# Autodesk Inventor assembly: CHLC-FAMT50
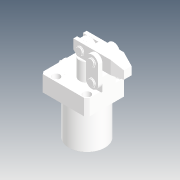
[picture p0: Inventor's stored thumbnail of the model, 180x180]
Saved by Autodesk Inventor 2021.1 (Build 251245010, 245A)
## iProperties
Created: 2019-04
Part Number: CHLC-FAMT50
Description: STEP AP214
Document SubType Name: Assembly
Designer: user
Title: CHLC-FAMT50.STEP
Revision Number: ÈÎºÎ
Sending System: SolidWorks 2016
Preprocessor: SwSTEP 2.0
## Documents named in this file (10)
- D:\Vault_2016\Projekty\Clamptek\Hydraulic\CHLC\CHLC-50\Inventor\CHLC-FAMT50\CHLC-FAMT50.iam
- D:\Vault_2016\Projekty\Clamptek\Hydraulic\CHLC\CHLC-50\Inventor\CHLC-FAMT50\CHLC-50-01.ipt
- D:\Vault_2016\Projekty\Clamptek\Hydraulic\CHLC\CHLC-50\Inventor\CHLC-FAMT50\CHLC-50-02.ipt
- D:\Vault_2016\Projekty\Clamptek\Hydraulic\CHLC\CHLC-50\Inventor\CHLC-FAMT50\CHLC-50-03.ipt
- D:\Vault_2016\Projekty\Clamptek\Hydraulic\CHLC\CHLC-50\Inventor\CHLC-FAMT50\CHLC-50-04.ipt
- D:\Vault_2016\Projekty\Clamptek\Hydraulic\CHLC\CHLC-50\Inventor\CHLC-FAMT50\CHLC-50-06.ipt
- D:\Vault_2016\Projekty\Clamptek\Hydraulic\CHLC\CHLC-50\Inventor\CHLC-FAMT50\CHLC-50-09.ipt
- D:\Vault_2016\Projekty\Clamptek\Hydraulic\CHLC\CHLC-50\Inventor\CHLC-FAMT50\CHLC-FAMT50-01.ipt
- D:\Vault_2016\Projekty\Clamptek\Hydraulic\CHLC\CHLC-50\Inventor\CHLC-FAMT50\M6LS.ipt
- D:\Vault_2016\Projekty\Clamptek\Hydraulic\CHLC\CHLC-50\Inventor\CHLC-FAMT50\CZL20µ÷ËÙ·§.iam
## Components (18 placed, 18 different names)
1. CHLC-50-01_1
2. CHLC-50-02_2
3. CHLC-50-03_3
4. CHLC-50-04_4
5. CHLC-50-06_5
6. CHLC-50-09_6
7. CHLC-FAMT50-01_7
8. M6LS_8
9. M6LS_9
10. CHLC-50-04_10
11. CHLC-50-03_11
12. CHLC-50-06_12
13. CHLC-50-06_13
14. CHLC-50-06_14
15. CHLC-50-06_15
16. CHLC-50-06_16
17. M6LS_17
18. CZL20µ÷ËÙ·§_18 [sub-assembly]
